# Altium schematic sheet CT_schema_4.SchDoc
size 396 x 205 mm
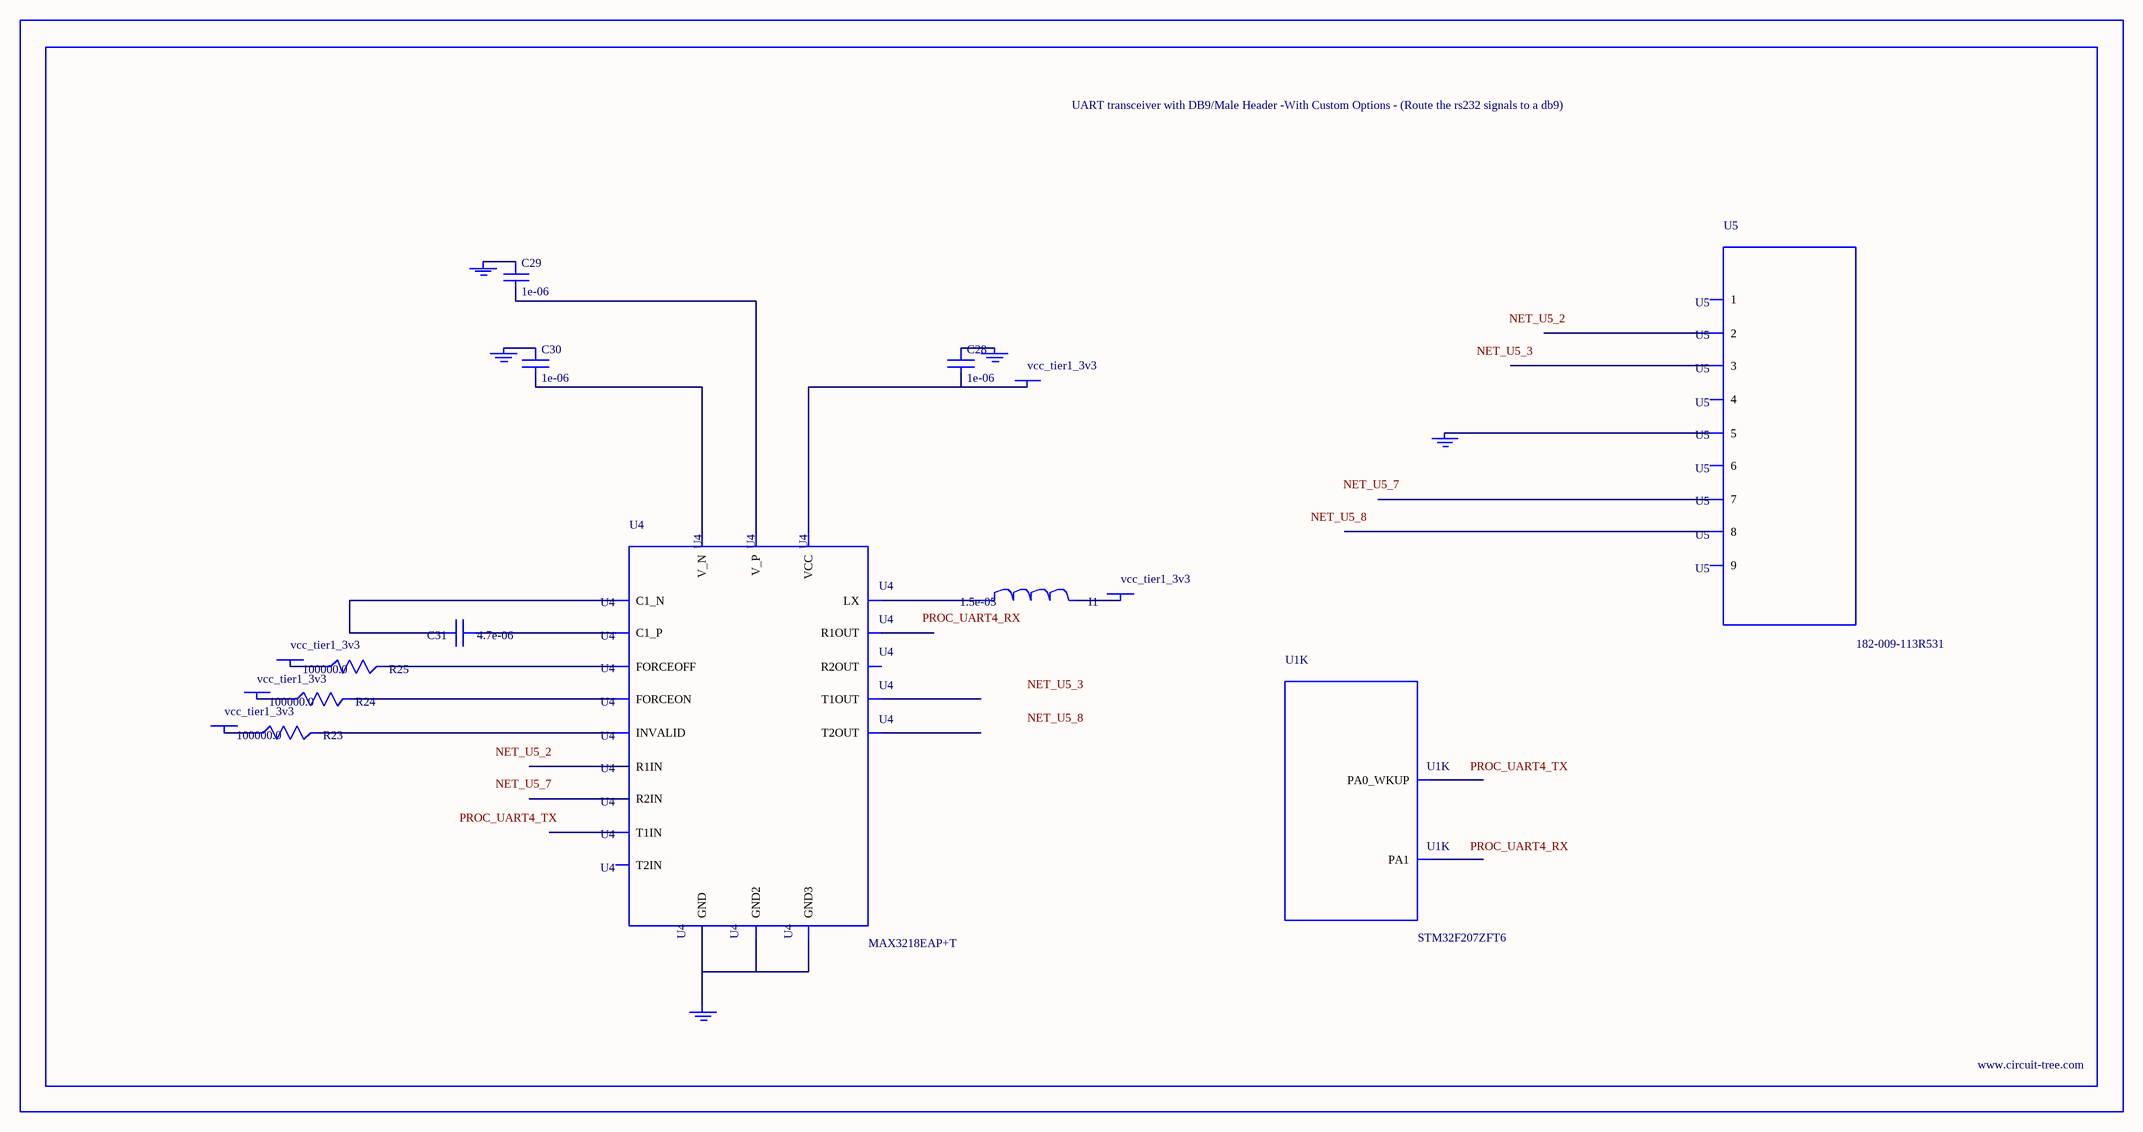
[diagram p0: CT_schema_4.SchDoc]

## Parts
BORDER3  (no value)
C28  1e-06  [C0603]
C29  1e-06  [C0603]
C30  1e-06  [C0603]
C31  4.7e-06  [C0805]
GND_INSTANCE_3_0  (no value)
GND_INSTANCE_3_1  (no value)
GND_INSTANCE_3_2  (no value)
GND_INSTANCE_3_3  (no value)
GND_INSTANCE_3_4  (no value)
I1  1.5e-05  [L1210]
POWER_INSTANCE_3_0  vcc_tier1_3v3
POWER_INSTANCE_3_1  vcc_tier1_3v3
POWER_INSTANCE_3_2  vcc_tier1_3v3
POWER_INSTANCE_3_3  vcc_tier1_3v3
POWER_INSTANCE_3_4  vcc_tier1_3v3
R23  100000.0  [R0603]
R24  100000.0  [R0603]
R25  100000.0  [R0603]
U1  STM32F207ZFT6  [LQFP144]  (part K of 13)
U4  MAX3218EAP+T  [SSOP-20]
U5  182-009-113R531  [182-009-MALE]

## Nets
NetC28_1: C28.1 GND_INSTANCE_3_0.0(GND)
NetC28_2: C28.2 POWER_INSTANCE_3_4.0(PWR) U4.6(VCC)
NetC29_1: C29.1 GND_INSTANCE_3_2.0(GND)
NetC29_2: C29.2 U4.19(V_P)
NetC30_1: C30.1 GND_INSTANCE_3_1.0(GND)
NetC30_2: C30.2 U4.15(V_N)
NetC31_1: C31.1 U4.18(C1_P)
NetC31_2: C31.2 U4.16(C1_N)
NetGND_INSTANCE_3_3_0: GND_INSTANCE_3_3.0(GND) U4.5(GND) U4.17(GND2) U4.20(GND3)
NetGND_INSTANCE_3_4_0: GND_INSTANCE_3_4.0(GND) U5.5
NetI1_1: I1.1 U4.1(LX)
NetI1_2: I1.2 POWER_INSTANCE_3_0.0(PWR)
NetPOWER_INSTANCE_3_1_0: POWER_INSTANCE_3_1.0(PWR) R23.1
NetPOWER_INSTANCE_3_2_0: POWER_INSTANCE_3_2.0(PWR) R24.1
NetPOWER_INSTANCE_3_3_0: POWER_INSTANCE_3_3.0(PWR) R25.1
NetR23_2: R23.2 U4.2(INVALID)
NetR24_2: R24.2 U4.3(FORCEON)
NetR25_2: R25.2 U4.4(FORCEOFF)

Not connected (* = marked no-connect by the designer): U1 34(PA0_WKUP) 35(PA1); U4 7(T1IN) 8(T2IN) 9(R1OUT) 10(R2OUT) 11(R2IN) 12(R1IN) 13(T2OUT) 14(T1OUT); U5 1 2 3 4 6 7 8 9

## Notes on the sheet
- Labels drawn without touching a wire or pin: NET_U5_2, NET_U5_3, NET_U5_7, NET_U5_8, PROC_UART4_RX, PROC_UART4_TX

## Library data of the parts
BORDER3 = BORDER_PAGE3
C28-C30 = C0603C105K3RACTU
C31 = C0805C475K4RACTU
GND_INSTANCE_3_0-GND_INSTANCE_3_4 = GND
I1 = L1210R150MDWIT
POWER_INSTANCE_3_0-POWER_INSTANCE_3_4 = PWR
R23-R25 = RC0603JR-07100KL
